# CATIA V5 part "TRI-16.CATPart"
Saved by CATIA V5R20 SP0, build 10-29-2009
Part number: _TRI-16
Definition: NONE
Nomenclature: _TRI-16
Source: Unknown
Description: PART-_TRI-16-DESC
Bounding box of the stored display mesh (mm): x 0 to 22, y -8 to 8, z -8 to 8
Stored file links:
  C:\Users\Utente\Desktop\IO LAVORO\3D X SITO CF\X SITO\PLASTICA\TRI\TRI-16.CATPart
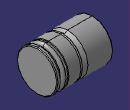
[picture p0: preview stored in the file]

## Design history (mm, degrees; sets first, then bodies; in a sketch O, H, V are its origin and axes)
Body1 "_TRI-16" (main body)
  Solid1: solid without history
